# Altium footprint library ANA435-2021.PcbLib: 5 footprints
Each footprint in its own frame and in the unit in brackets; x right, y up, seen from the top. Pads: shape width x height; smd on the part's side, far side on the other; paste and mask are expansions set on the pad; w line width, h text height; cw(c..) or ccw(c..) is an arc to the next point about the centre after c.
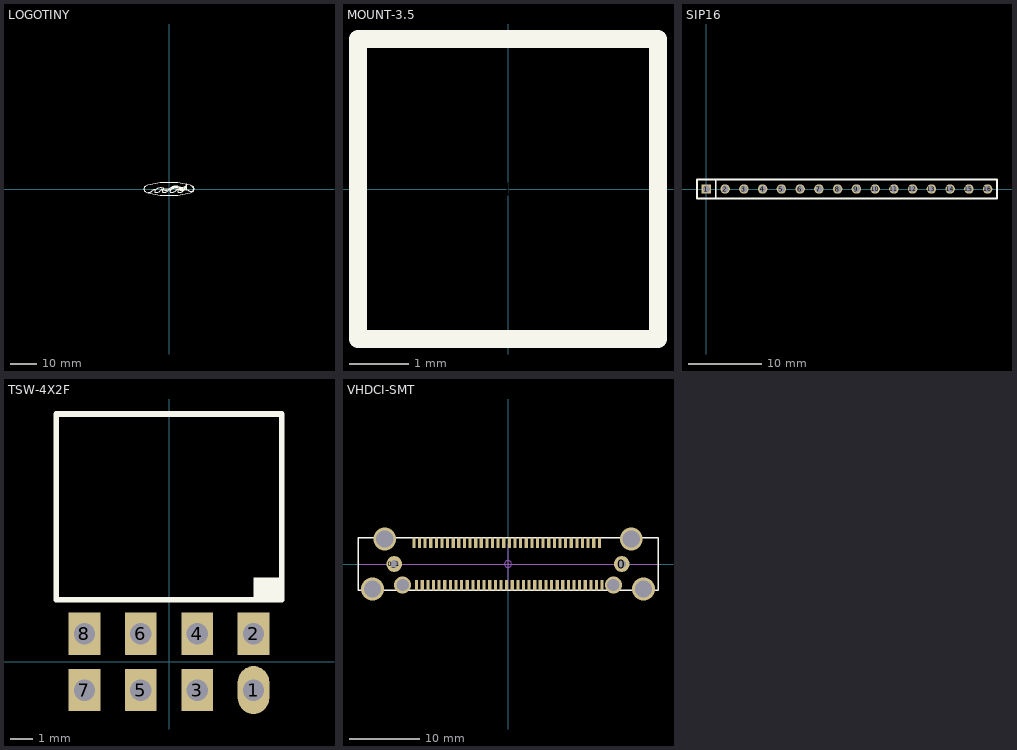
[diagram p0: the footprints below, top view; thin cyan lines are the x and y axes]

## LOGOTINY [mm]
Top Overlay:
  lines w0.127: -7.721,-1.287 ccw(c-7.683,0.851) -6.145,-0.635 ; -6.137,-0.657 cw(c-5.22,-1.575) -4.884,-0.321 ; -4.99,-0.226 cw(c-3.124,-2.794) -2.039,0.188 ; -4.863,-1.287 ccw(c-4.826,0.851) -3.288,-0.635 ; -4.851,-1.295 cw(c-4.851,-0.813) -4.851,-0.33 ; -3.28,-0.657 cw(c-2.362,-1.575) -2.026,-0.321 ; -2.165,-0.252 ccw(c-1.079,2.73) 0.786,0.163 ; -2.051,0.193 ccw(c-0.965,3.175) 0.9,0.607 ; -2.007,-1.295 cw(c-2.007,-0.813) -2.007,-0.33 ; -1.993,-1.275 ccw(c-1.956,0.864) -0.417,-0.622 ; -0.422,-0.657 cw(c0.495,-1.575) 0.831,-0.321 ; 0.675,-0.29 cw(c2.54,-2.857) 3.625,0.125 ; 0.675,0.091 cw(c2.54,-2.476) 3.625,0.506 ; 0.675,0.472 cw(c2.54,-2.095) 3.625,0.887 ; 0.851,-1.295 cw(c0.851,-0.813) 0.851,-0.33 ; 0.852,-1.287 ccw(c0.889,0.851) 2.427,-0.635 ; 2.435,-0.657 cw(c3.353,-1.575) 3.689,-0.321 ; 3.614,-0.252 ccw(c4.699,2.73) 6.564,0.163 ; 3.614,0.129 ccw(c4.699,3.111) 6.564,0.544 ; 3.614,0.51 ccw(c4.699,3.492) 6.564,0.925 ; 3.614,0.891 ccw(c4.699,3.873) 6.564,1.306 ; 3.734,-1.295 cw(c3.734,-0.813) 3.734,-0.33 ; 3.747,-1.287 ccw(c3.785,0.851) 5.323,-0.635 ; 5.254,-0.657 cw(c6.172,-1.575) 6.172,-0.277 ; 6.159,-0.318 6.985,-0.318 ; 6.528,-0.318 6.528,1.956 ; 6.992,-0.325 ccw(c8.255,0.699) 8.993,-0.75 ; 8.302,1.16 cw(c7.925,0) 8.692,-0.947
  lines w0.203: -8.755,-1.04 cw(c-8.026,0) -8.755,1.04 ; -8.697,-1.082 ccw(c0,26.67) 8.697,-1.082 ; -8.697,1.082 cw(c0,-26.67) 8.697,1.082 ; 8.755,-1.04 ccw(c8.026,0) 8.755,1.04

## MOUNT-3.5 [mm]
pads (1):
  round 5.08 on Mech1: 1(0,0)
Top Overlay:
  lines w0.305: -2.54,-2.54 -2.54,2.54 2.54,2.54 2.54,-2.54 -2.54,-2.54
Mechanical 1:
  text "3.5MM" at -3.81,2.54 h1.02

## SIP16 [mil]
pads (16):
  rect 50x50 hole 36: 1(0,0)
  round 50 hole 36: 2(100,0) 3(200,0) 4(300,0) 5(400,0) 6(500,0) 7(600,0) 8(700,0) 9(800,0) 10(900,0) 11(1000,0) 12(1100,0) 13(1200,0) 14(1300,0) 15(1400,0) 16(1500,0)
Top Overlay:
  lines w10: 50,-50 50,50 ; -50,-50 1550,-50 1550,50 -50,50 -50,-50

## TSW-4X2F [mil]
pads (8):
  oval 56x85 hole 38: 1(150,-50)
  rect 56x75 hole 38: 2(150,50) 3(50,-50) 4(50,50) 5(-50,-50) 6(-50,50) 7(-150,-50) 8(-150,50)
Top Overlay:
  region: 200,150 150,150 150,110 200,110
  lines w10: -200,110 -200,440 200,440 200,110 -200,110
Mechanical 1:
  text "TSW-4X2F" at -150,200 h40

## VHDCI-SMT [mm]
pads (70):
  round 2.25 hole 1.2: 0(16.2,0) 0_1(-16.2,0)
  rect 0.45x1.5 smd: 1(13,3) 2(12.2,3) 3(11.4,3) 4(10.6,3) 5(9.8,3) 6(9,3) 7(8.2,3) 8(7.4,3) 9(6.6,3) 10(5.8,3) 11(5,3) 12(4.2,3) 13(3.4,3) 14(2.6,3) 15(1.8,3) 16(1,3) 17(0.2,3) 18(-0.6,3) 19(-1.4,3) 20(-2.2,3) 21(-3,3) 22(-3.8,3) 23(-4.6,3) 24(-5.4,3) 25(-6.2,3) 26(-7,3) 27(-7.8,3) 28(-8.6,3) 29(-9.4,3) 30(-10.2,3) 31(-11,3) 32(-11.8,3) 33(-12.6,3) 34(-13.4,3) 35(13.4,-3) 36(12.6,-3) 37(11.8,-3) 38(11,-3) 39(10.2,-3) 40(9.4,-3) 41(8.6,-3) 42(7.8,-3) 43(7,-3) 44(6.2,-3) 45(5.4,-3) 46(4.6,-3) 47(3.8,-3) 48(3,-3) 49(2.2,-3) 50(1.4,-3) 51(0.6,-3) 52(-0.2,-3) 53(-1,-3) 54(-1.8,-3) 55(-2.6,-3) 56(-3.4,-3) 57(-4.2,-3) 58(-5,-3) 59(-5.8,-3) 60(-6.6,-3) 61(-7.4,-3) 62(-8.2,-3) 63(-9,-3) 64(-9.8,-3) 65(-10.6,-3) 66(-11.4,-3) 67(-12.2,-3) 68(-13,-3)
via -19.27,-3.55 diameter 3.24 hole 2.44
via -17.54,3.55 diameter 3.24 hole 2.44
via -15,-3 diameter 2.4 hole 1.75
via 15,-3 diameter 2.4 hole 1.75
via 19.27,-3.55 diameter 3.24 hole 2.44
via 17.54,3.55 diameter 3.24 hole 2.44
Top Overlay:
  lines w0.203: -21.35,-3.73 21.35,-3.73 21.35,3.73 -21.35,3.73 -21.35,-3.73
Top Paste:
  region: -15.367,-0.762 -15.367,0.762 -17.018,0.762 -17.018,-0.762
  region: 17.018,-0.762 17.018,0.762 15.367,0.762 15.367,-0.762
  region: 15.748,-3.81 15.748,-2.286 14.097,-2.286 14.097,-3.81
  region: -14.224,-3.683 -14.224,-2.159 -15.875,-2.159 -15.875,-3.683
  region: 20.701,-4.826 20.701,-2.286 17.907,-2.286 17.907,-4.826
  region: 18.923,2.286 18.923,4.826 16.129,4.826 16.129,2.286
  region: -17.907,-4.699 -17.907,-2.159 -20.701,-2.159 -20.701,-4.699
Mechanical 2:
  circle w0.15: c0,0 r0.5
  lines w0.102: -21.336,0 21.336,0 ; 0,-3.6 0,2.9
  text "68" at -13.9,-1.7 h1
  text "35" at 12,-1.8 h1
  text "34" at -14.2,0.9 h1
  text "1" at 12.8,0.5 h1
